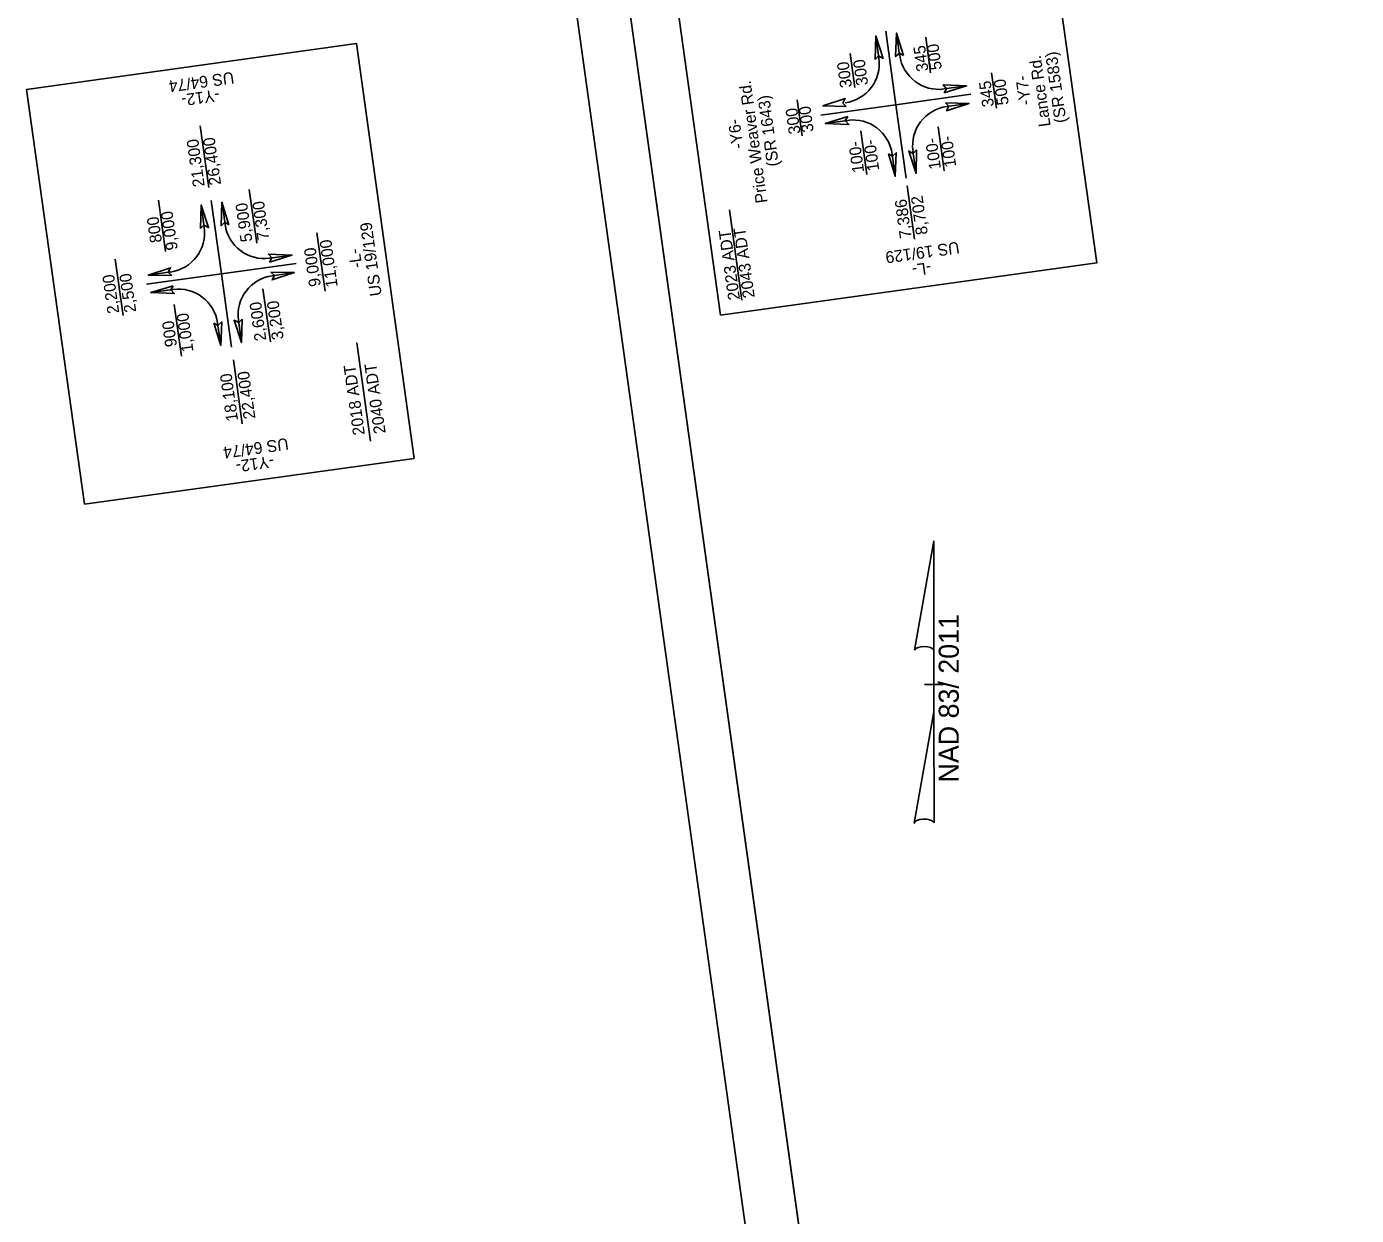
# Model space of a CAD drawing. Extents: x 477151 to 478666, y 496366 to 498184.
# Drawn here: x 477151 to 477715, y 497275 to 497779 of the extents above; entities that cross this region are included whole.
import ezdxf

# ---------------------------------------------------------------- set-up
doc = ezdxf.new("R2010")
doc.units = 0
for name, color, linetype in [('Prop DSN Text', 7, 'Continuous'), ('Prop Grid Mask', 7, 'Continuous'), ('Prop North Arrow NAD83 for Plan Sheets CELL', 7, 'Continuous'), ('Prop PHM Traffic Signal CELL', 7, 'Continuous'), ('Sheet Clip Boundary CELL', 7, 'Continuous'), ('Sheet Plan CELL', 7, 'Continuous'), ('Sheet Plot Border Outside CELL', 7, 'Continuous')]:
    doc.layers.add(name, color=color, linetype=linetype)

msp = doc.modelspace()

# ---------------------------------------------------------------- linework, layer by layer
at = {"layer": 'Prop DSN Text'}
for p, q in [((477540.15, 497752.86), (477549.58, 497754.16)), ((477487.83, 497741.77), (477519.64, 497746.2)), ((477551.45, 497750.63), (477519.64, 497746.2)), ((477541.18, 497745.41), (477550.62, 497746.72)), ((477489.67, 497738.25), (477499.11, 497739.56)), ((477265.31, 497678.87), (477233.5, 497674.44)), ((477254, 497681.1), (477263.44, 497682.4)), ((477201.69, 497670.01), (477233.5, 497674.44)), ((477202.51, 497673.92), (477211.95, 497675.23)), ((477255.04, 497673.65), (477264.48, 497674.96)), ((477203.53, 497666.49), (477212.97, 497667.8))]:
    msp.add_line(p, q, dxfattribs=at)
for points in [[(477510.85, 497765.39), (477511.1, 497775.34), (477514.21, 497765.85), (477512.27, 497766.85)], [(477522.86, 497767.06), (477519.91, 497776.57), (477519.5, 497766.59), (477521.09, 497768.07)], [(477540.09, 497751.21), (477549.6, 497754.16), (477539.62, 497754.57), (477541.11, 497752.98)], [(477498.6, 497745.44), (477488.65, 497745.68), (477498.14, 497748.8), (477497.14, 497746.86)], [(477540.68, 497746.96), (477550.64, 497746.72), (477541.15, 497743.6), (477542.14, 497745.54)], [(477499.19, 497741.19), (477489.69, 497738.24), (477499.67, 497737.83), (477498.18, 497739.43)], [(477516.43, 497725.34), (477519.38, 497715.83), (477519.79, 497725.81), (477518.19, 497724.33)], [(477528.43, 497727.01), (477528.19, 497717.06), (477525.07, 497726.55), (477527.01, 497725.55)], [(477224.71, 497693.63), (477224.96, 497703.58), (477228.07, 497694.09), (477226.13, 497695.09)], [(477236.72, 497695.3), (477233.76, 497704.81), (477233.36, 497694.83), (477234.95, 497696.32)], [(477253.95, 497679.45), (477263.46, 497682.41), (477253.48, 497682.81), (477254.97, 497681.22)], [(477212.46, 497673.68), (477202.51, 497673.92), (477212, 497677.04), (477211, 497675.1)], [(477254.54, 497675.2), (477264.49, 497674.96), (477255.01, 497671.84), (477256, 497673.78)], [(477213.05, 497669.43), (477203.55, 497666.48), (477213.52, 497666.07), (477212.04, 497667.67)], [(477230.28, 497653.58), (477233.24, 497644.08), (477233.65, 497654.05), (477232.05, 497652.57)], [(477242.29, 497655.25), (477242.05, 497645.3), (477238.93, 497654.79), (477240.87, 497653.79)]]:
    msp.add_lwpolyline(points, close=True, dxfattribs=at)
for centre, start, end in [((477495.79, 497763.6), 277.8775, 7.8775), ((477537.84, 497769.46), 187.9677, 277.9677), ((477543.5, 497728.8), 97.8775, 187.8775), ((477501.45, 497722.95), 7.9677, 97.9677), ((477251.7, 497697.7), 187.9677, 277.9677), ((477209.65, 497691.84), 277.8775, 7.8775), ((477257.36, 497657.04), 97.8775, 187.8775), ((477215.31, 497651.19), 7.9677, 97.9677)]:
    msp.add_arc(centre, 16.77, start, end, dxfattribs=at)
at = {"layer": 'Prop Grid Mask'}
for points in [[(477445.17, 497656.87), (477423.68, 497811.31), (477583.3, 497833.52), (477604.8, 497679.08)], [(477175.39, 497576.71), (477150.89, 497752.7), (477290.77, 497772.16), (477315.26, 497596.17)]]:
    msp.add_lwpolyline(points, close=True, dxfattribs=at)
at = {"layer": 'Prop North Arrow NAD83 for Plan Sheets CELL'}
for p, q in [((477527.53, 497514.88), (477535.73, 497561.23)), ((477535.78, 497561.23), (477535.73, 497561.23)), ((477535.78, 497561.23), (477535.73, 497561.23)), ((477535.78, 497561.23), (477535.78, 497513.43)), ((477535.78, 497488.63), (477535.78, 497514.83)), ((477535.78, 497513.43), (477535.78, 497514.78)), ((477531.78, 497500.23), (477531.73, 497500.23)), ((477535.33, 497500.23), (477531.78, 497500.23)), ((477531.83, 497500.23), (477539.83, 497500.23)), ((477535.78, 497488.63), (477527.43, 497441.38)), ((477535.83, 497441.58), (477535.78, 497488.63))]:
    msp.add_line(p, q, dxfattribs=at)
for centre, start_param, end_param in [((477531.66, 497514.39), 0.216388, 2.908219), ((477531.66, 497441.22), 0.201328, 3.141593)]:
    msp.add_ellipse(centre, major_axis=(4.23, -0.03), ratio=0.461098, start_param=start_param, end_param=end_param, dxfattribs=at)
at = {"layer": 'Prop PHM Traffic Signal CELL'}
for p, q in [((477512.39, 497765.98), (477511.09, 497775.42)), ((477515.31, 497777.34), (477519.64, 497746.2)), ((477521.23, 497767.13), (477519.92, 497776.57)), ((477532.28, 497774.84), (477534.37, 497759.76)), ((477500.21, 497767.96), (477502.23, 497753.44)), ((477560.19, 497759.64), (477562.25, 497744.78)), ((477477.77, 497748.21), (477479.9, 497732.92)), ((477523.98, 497715.06), (477519.64, 497746.2)), ((477228.18, 497711.02), (477224.54, 497737.2)), ((477507.32, 497716.63), (477504.76, 497735.09)), ((477540.16, 497718.18), (477537.57, 497736.78)), ((477519.37, 497715.83), (477518.06, 497725.27)), ((477528.19, 497717.06), (477526.88, 497726.5)), ((477248.52, 497687.39), (477245.34, 497710.26)), ((477527.59, 497689.13), (477524.44, 497711.74)), ((477209.83, 497683.88), (477206.8, 497705.63)), ((477226.25, 497694.22), (477224.95, 497703.66)), ((477229.17, 497705.58), (477233.5, 497674.44)), ((477229.17, 497705.58), (477233.5, 497674.44)), ((477235.09, 497695.37), (477233.78, 497704.81)), ((477448.99, 497701.63), (477454.34, 497663.23)), ((477274.05, 497691.81), (477277.5, 497667.05)), ((477188.53, 497680.68), (477191.85, 497656.81)), ((477237.83, 497643.3), (477233.5, 497674.44)), ((477237.83, 497643.3), (477233.5, 497674.44)), ((477251.15, 497668.15), (477254.3, 497645.55)), ((477213.52, 497661.4), (477216.57, 497639.48)), ((477233.22, 497644.07), (477231.92, 497653.51)), ((477242.05, 497645.3), (477240.74, 497654.74)), ((477290.95, 497645.2), (477296.75, 497603.49)), ((477238.6, 497637.94), (477242.38, 497610.77))]:
    msp.add_line(p, q, dxfattribs=at)
msp.add_lwpolyline([(477175.39, 497576.71), (477150.89, 497752.7), (477290.77, 497772.16), (477315.26, 497596.17)], close=True, dxfattribs=at)
at = {"layer": 'Sheet Clip Boundary CELL'}
msp.add_lwpolyline([(477521.55, 496961.07), (477576.76, 496564.39), (477581, 496533.88), (477980.85, 496589.53), (477967.1, 496688.28), (477990.56, 496691.36), (478608.23, 496770.21), (478458.67, 497790.41), (478383.4, 497784.94), (478355.71, 497983.96), (478358.48, 497984.34), (478349.14, 498051.47), (477730.12, 497965.32), (477560.31, 497941.69), (477573.71, 497845.37), (477401.82, 497821.44)], close=True, dxfattribs=at)
at = {"layer": 'Sheet Plan CELL'}
msp.add_lwpolyline([(477374.24, 498019.6), (477581, 496533.88), (478620.98, 496678.61), (478414.22, 498164.31)], close=True, dxfattribs=at)
at = {"layer": 'Sheet Plot Border Outside CELL'}
msp.add_lwpolyline([(478666.23, 496516.82), (478434.18, 498184.25), (477349.63, 498033.32), (477581.68, 496365.89)], close=True, dxfattribs=at)

# ---------------------------------------------------------------- texts
at = {"layer": 'Prop North Arrow NAD83 for Plan Sheets CELL'}
msp.add_text('NAD 83/ 2011', height=8.5, rotation=90, dxfattribs=at).set_placement((477546.3, 497458.72))
at = {"layer": 'Prop PHM Traffic Signal CELL'}
for s, rotation, p in [('345', 97.9226, (477533.47, 497760.58)), ('500', 97.9226, (477539.16, 497761.27)), ('300', 97.9226, (477501.03, 497753.72)), ('300', 97.9226, (477507.89, 497754.67)), ('Lance Rd. ', 97.9226, (477585.26, 497737.17)), ('(SR 1583)', 97.9226, (477592.03, 497738.79)), ('US 64/74', 187.9227, (477238.53, 497760.2)), ('-Y7-', 97.9226, (477576.98, 497746.32)), ('-Y12-', 187.9227, (477232.43, 497752.73)), ('Price Weaver Rd. ', 97.9226, (477465.19, 497704.77)), ('345', 97.9226, (477561.29, 497745.58)), ('500', 97.9226, (477567.53, 497746.35)), ('(SR 1643)', 97.9226, (477470.03, 497720.31)), ('300', 97.9226, (477479.24, 497734.06)), ('300', 97.9226, (477484.81, 497734.84)), ('-Y6-', 97.9226, (477454.99, 497727.84)), ('21,300', 97.9226, (477226.49, 497711.67)), ('26,400', 97.9226, (477233.42, 497712.38)), ('100-', 97.9226, (477506.2, 497717.66)), ('100-', 97.9226, (477512.63, 497718.39)), ('100-', 97.9225, (477538.76, 497719.09)), ('100-', 97.9225, (477545.26, 497719.99)), ('8,702', 97.9226, (477533.19, 497691.33)), ('9,000', 98.0128, (477215.05, 497684.79)), ('5,900', 97.9226, (477246.7, 497688.3)), ('7,300', 97.9226, (477253.87, 497689.01)), ('7,386', 97.9226, (477526.34, 497689.85)), ('800', 98.0128, (477208.32, 497687.96)), ('US 19/129', 97.9226, (477301.55, 497665.32)), ('2023 ADT', 97.9226, (477453.52, 497663.64)), ('2043 ADT', 97.9226, (477459.79, 497664.52)), ('9,000', 97.9226, (477275.74, 497669.33)), ('11,000', 97.9226, (477282.9, 497669.03)), ('-L-', 97.9226, (477293.27, 497677.31)), ('US 19/129', 187.9227, (477546.21, 497688.15)), ('-L-', 187.9227, (477534.27, 497679.49)), ('2,200', 97.9226, (477190.23, 497657.9)), ('2,500', 97.9226, (477197.43, 497658.36)), ('2,600', 97.9226, (477252.64, 497646.31)), ('3,200', 97.9226, (477260.01, 497646.82)), ('1,000', 97.8324, (477221.71, 497641.56)), ('900', 97.8324, (477214.74, 497643.78)), ('2018 ADT', 97.9226, (477294.41, 497606.33)), ('2040 ADT', 97.9226, (477303.23, 497606.95)), ('18,100', 97.9226, (477240.62, 497612.23)), ('22,400', 97.9226, (477247.98, 497613.19)), ('US 64/74', 187.9227, (477261.63, 497604.87)), ('-Y12-', 187.9227, (477255.52, 497597.4))]:
    msp.add_text(s, height=5, rotation=rotation, dxfattribs=at).set_placement(p)

doc.saveas('drawing.dxf')
